Omron CX-Programmer project NewProject (CX-Programmer 9.41)

# PLC NewPLC1: CJ2M CPU12
I/O table (CPU CJ2M-CPU12): rack 0 slot 0 CJ1W-ETN21(ETN21Mode)

## Program NewProgram1 (cyclic task 0)
Local symbols
ETN_CloseRequest 1522.13 BOOL  ; ETN Unit close request dedicated control bit
ETN_DestinationIPAddress2 D30091 UINT  ; ETN Unit destination IP address
ETN_DestinationPortNo D30092 UINT  ; ETN Unit destination port No.
ETN_LocalPortNo D30089 UINT  ; ETN Unit local port No.
ETN_NoOfBytesToSendReceive D30093 INT  ; ETN Unit No. of bytes to send/receive
ETN_OpenRequest 1522.10 BOOL  ; ETN Unit TCP open request (ACTIVE) dedicated control bit
ETN_ReceiveData 1516.13 BOOL  ; ETN Unit receive data presence/absence detection bit
ETN_ReceiveRequest 1522.12 BOOL  ; ETN Unit receive request dedicated control bit
ETN_ResponseCode D30097 UINT  ; ETN Unit response code
ETN_SendReceiveDataAddress1 D30094 UINT  ; ETN Unit send/receive data address
ETN_SendReceiveDataAddress2 D30095 UINT  ; ETN Unit send/receive data address
ETN_SendRequest 1522.11 BOOL  ; ETN Unit send request dedicated control bit
ETN_SocketNo8 D30088 UINT  ; ETN Unit socket option/socket No.8
ETN_TCPConnectionStatus D30016 UINT  ; ETN Unit TCP connection status
ETN_TCPNoOfBytesToReceive D30008 UINT  ; ETN Unit TCP No of bytes to receive
ETN_TimeoutValue D30096 UINT  ; ETN Unit timeout value
Input_CloseMonitoringTime_BCD 5013 UINT_BCD  ; Close monitoring time (BCD)
Input_NoOfBytesToSend D9000 UINT  ; No. of bytes to send
Input_OpenMonitoringTime_BCD 5010 UINT_BCD  ; Open monitoring time (BCD)
Input_ReceiveMonitoringTime_BCD 5012 UINT_BCD  ; Receive monitoring time (BCD)
Input_ReceiveProcessingRequiredNotRequired 5020 UINT  ; Receive processing required/not required setting for send processing
Input_ReceiveWaitingTime_BIN 5014 UINT  ; Receive waiting time (BIN)
Input_SendData D9001 WORD[128]  ; Send data
Input_SendMonitoringTime_BCD 5011 UINT_BCD  ; Send monitoring time (BCD)
Input_Start 5000.00 BOOL  ; Communication processing start switch (turn ON manually)
Local_CloseErrorEnd 5004.02 BOOL  ; Error end->[Communications end]
Local_CloseExecuting 5004.00 BOOL  ; Retain ON status until close processing is completed
Local_CloseMonitoringTimerON T1003 BOOL  ; Close processing monitoring timer
Local_CloseNormalEnd 5004.01 BOOL  ; Normal end->[Communications end]
Local_CloseResponseCodeError 5004.03 BOOL  ; Response code error
Local_CloseStatusError 5004.05 BOOL  ; TCP close status error
Local_CloseTimeout 5004.04 BOOL  ; Timeout
Local_CommunicationsInProgress 5000.01 BOOL  ; Retain ON status until communication processing is completed->[Open processing]
Local_FirstReceiveWord 5111 INT  ; First receive word
Local_FirstReceiveWordDivisionRemainder 5113 INT  ; First receive word division remainder
Local_FirstReceiveWordOffset 5112 INT  ; First receive word offset
Local_FirstSendWord 5031 UINT  ; First send word
Local_InitialSettingCompleted 5000.04 BOOL  ; Initialization setting completion->[Open processing]
Local_OpenErrorEnd 5001.02 BOOL  ; Error end->[Close processing]
Local_OpenExecuting 5001.00 BOOL  ; Retain ON status until open processing is completed
Local_OpenMonitoringTimerON T1000 BOOL  ; Open processing monitoring timer
Local_OpenNormalEnd 5001.01 BOOL  ; Normal end->[Send processing]
Local_OpenResponseCodeError 5001.03 BOOL  ; Response code error
Local_OpenTimeout 5001.04 BOOL  ; Timeout
Local_ReceiveDataAddressType 5110 UINT  ; Receive data address type
Local_ReceiveDataJudgmentArea_UNIT 5114 UINT  ; Area used to convert receive data into UNIT type and to determine the result
Local_ReceiveDestinationDeviceError 5003.05 BOOL  ; Destination device error
Local_ReceiveErrorEnd 5003.02 BOOL  ; Error end->[Close processing]
Local_ReceiveExecuting 5003.00 BOOL  ; Retain ON status until receive processing is completed
Local_ReceiveMonitoringTimerON T1002 BOOL  ; Receive processing monitoring timer
Local_ReceiveNormalEnd 5003.01 BOOL  ; Normal end->[Close processing]
Local_ReceiveProcessingNotRequired 5000.03 BOOL  ; After send processing, skip receive processing and executes close processing
Local_ReceiveProcessingRequired 5000.02 BOOL  ; After send processing, execute receive processing
Local_ReceiveRepeatON 5003.06 BOOL  ; Repeat receive request
Local_ReceiveRequestON 5003.07 BOOL  ; Receive request repeating ON<->OFF bit
Local_ReceiveResponseCodeError 5003.03 BOOL  ; Response code error
Local_ReceiveTimeout 5003.04 BOOL  ; Timeout
Local_SendDataAddressType 5030 UINT  ; Send data address type
Local_SendErrorEnd 5002.02 BOOL  ; Error end->[Close processing]
Local_SendExecuting 5002.00 BOOL  ; Retain ON status until send processing is completed
Local_SendMonitoringTimerON T1001 BOOL  ; Send processing monitoring timer
Local_SendNormalEnd 5002.01 BOOL  ; Normal end->[Receive processing]
Local_SendResponseCodeError 5002.03 BOOL  ; Response code error
Local_SendTimeout 5002.04 BOOL  ; Timeout
Local_TCPConnectionStatus 5005 UINT  ; TCP connection status determination area
Output_CloseErrorCode H404 WORD  ; Close processing response code/timeout code
Output_DestinationDeviceErrorCode H403 WORD  ; Destination device response code/error code
Output_NoOfBytesToReceive D10000 INT  ; No. of bytes to receive storage area
Output_OpenErrorCode H400 WORD  ; Open processing response code/timeout code
Output_ReceiveData D10001 WORD[2000]  ; Receive data storage area
Output_ReceiveErrorCode H402 WORD  ; Receive processing response code/timeout code
Output_SendErrorCode H401 WORD  ; Send processing response code/timeout code
TN_DestinationIPAddress1 D30090 UINT  ; ETN Unit destination IP address

### Section Start_Set

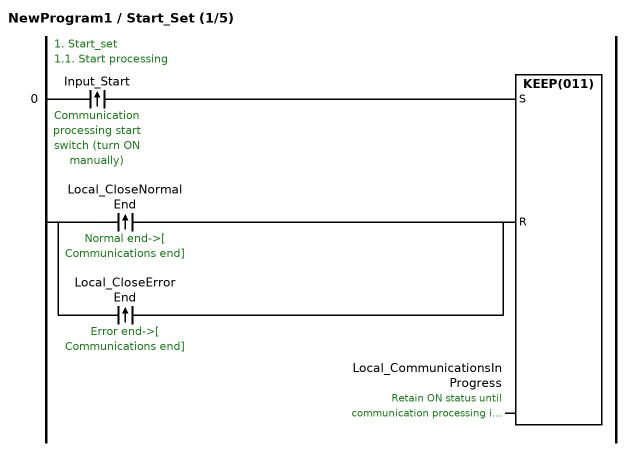
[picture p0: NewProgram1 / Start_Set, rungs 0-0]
; rung 0: 1. Start_set / 1.1. Start processing
@LD Input_Start  ; Communication processing start switch (turn ON manually)
@LD Local_CloseNormalEnd  ; Normal end->[Communications end]
@OR Local_CloseErrorEnd  ; Error end->[Communications end]
KEEP(011) Local_CommunicationsInProgress  ; Retain ON status until communication processing is completed->[Open processing]

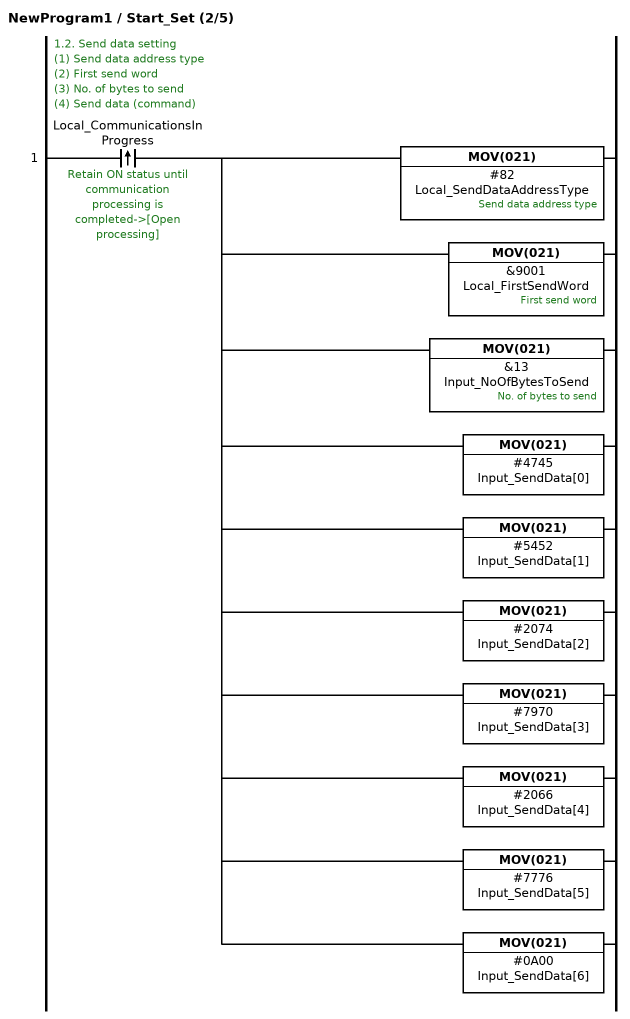
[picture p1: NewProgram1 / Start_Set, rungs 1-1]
; rung 1: 1.2. Send data setting / (1) Send data address type / (2) First send word / (3) No. of bytes to send / (4) Send data (command)
@LD Local_CommunicationsInProgress  ; Retain ON status until communication processing is completed->[Open processing]
MOV(021) #82 Local_SendDataAddressType  ; Send data address type
MOV(021) &9001 Local_FirstSendWord  ; First send word
MOV(021) &13 Input_NoOfBytesToSend  ; No. of bytes to send
MOV(021) #4745 Input_SendData[0]
MOV(021) #5452 Input_SendData[1]
MOV(021) #2074 Input_SendData[2]
MOV(021) #7970 Input_SendData[3]
MOV(021) #2066 Input_SendData[4]
MOV(021) #7776 Input_SendData[5]
MOV(021) #0A00 Input_SendData[6]

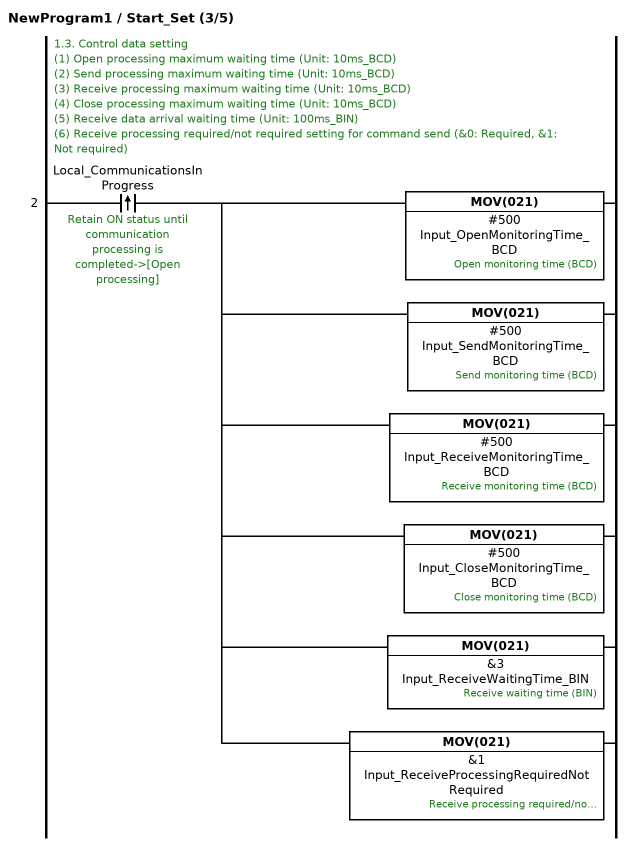
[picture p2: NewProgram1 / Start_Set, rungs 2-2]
; rung 2: 1.3. Control data setting / (1) Open processing maximum waiting time (Unit: 10ms_BCD) / (2) Send processing maximum waiting time (Unit: 10ms_BCD) / (3) Receive processing maximum waiting time (Unit: 10ms_BCD) / (4) Close processing maximum waiting time (Unit: 10ms_BCD) / (5) Receive data arrival waiting time (Unit: 100ms_BIN) / (6) Receive processing required/not required setting for command send (&0: Required, &1: Not required)
@LD Local_CommunicationsInProgress  ; Retain ON status until communication processing is completed->[Open processing]
MOV(021) #500 Input_OpenMonitoringTime_BCD  ; Open monitoring time (BCD)
MOV(021) #500 Input_SendMonitoringTime_BCD  ; Send monitoring time (BCD)
MOV(021) #500 Input_ReceiveMonitoringTime_BCD  ; Receive monitoring time (BCD)
MOV(021) #500 Input_CloseMonitoringTime_BCD  ; Close monitoring time (BCD)
MOV(021) &3 Input_ReceiveWaitingTime_BIN  ; Receive waiting time (BIN)
MOV(021) &1 Input_ReceiveProcessingRequiredNotRequired  ; Receive processing required/not required setting for send processing

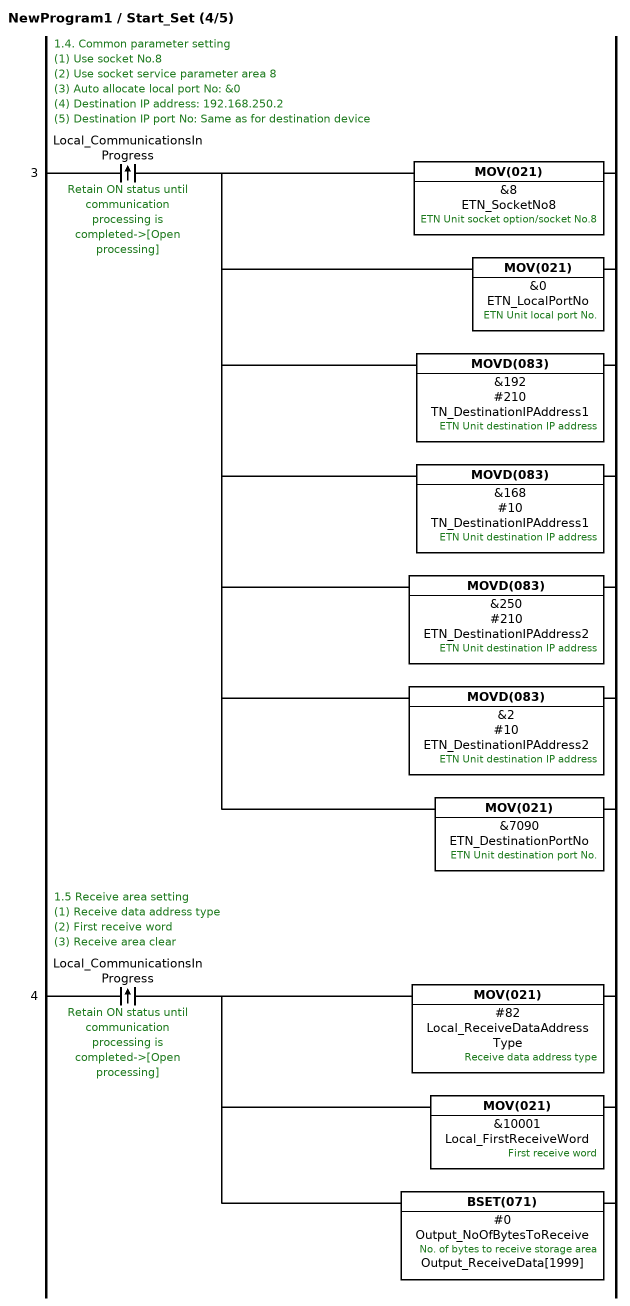
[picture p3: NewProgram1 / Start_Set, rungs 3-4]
; rung 3: 1.4. Common parameter setting / (1) Use socket No.8 / (2) Use socket service parameter area 8 / (3) Auto allocate local port No: &0 / (4) Destination IP address: 192.168.250.2 / (5) Destination IP port No: Same as for destination device
@LD Local_CommunicationsInProgress  ; Retain ON status until communication processing is completed->[Open processing]
MOV(021) &8 ETN_SocketNo8  ; ETN Unit socket option/socket No.8
MOV(021) &0 ETN_LocalPortNo  ; ETN Unit local port No.
MOVD(083) &192 #210 TN_DestinationIPAddress1  ; ETN Unit destination IP address
MOVD(083) &168 #10 TN_DestinationIPAddress1  ; ETN Unit destination IP address
MOVD(083) &250 #210 ETN_DestinationIPAddress2  ; ETN Unit destination IP address
MOVD(083) &2 #10 ETN_DestinationIPAddress2  ; ETN Unit destination IP address
MOV(021) &7090 ETN_DestinationPortNo  ; ETN Unit destination port No.
; rung 4: 1.5 Receive area setting / (1) Receive data address type / (2) First receive word / (3) Receive area clear
@LD Local_CommunicationsInProgress  ; Retain ON status until communication processing is completed->[Open processing]
MOV(021) #82 Local_ReceiveDataAddressType  ; Receive data address type
MOV(021) &10001 Local_FirstReceiveWord  ; First receive word
BSET(071) #0 Output_NoOfBytesToReceive Output_ReceiveData[1999]  ; No. of bytes to receive storage area

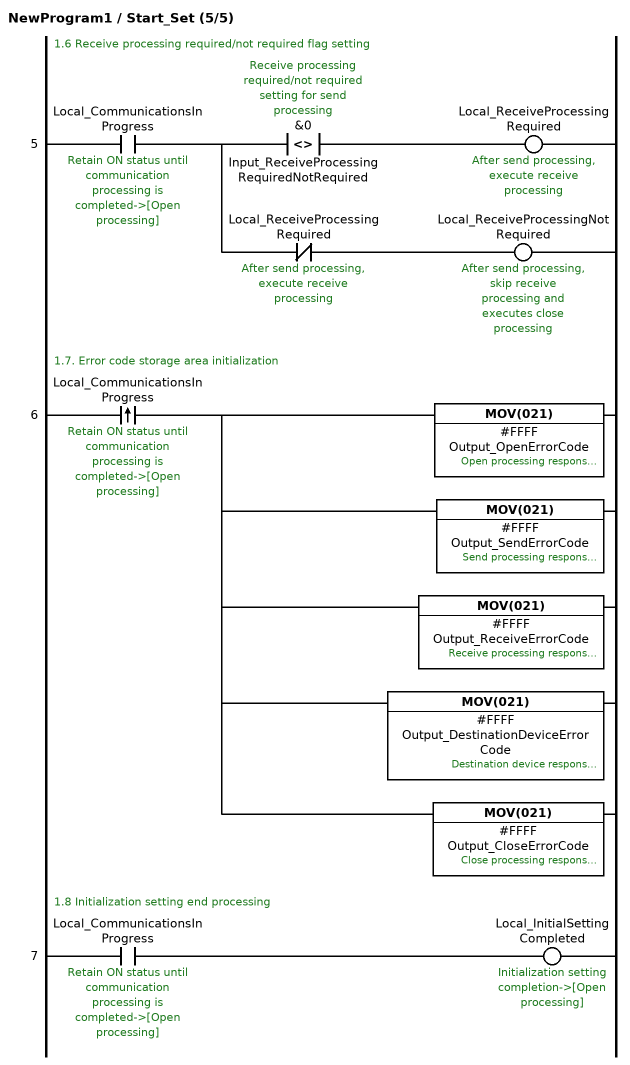
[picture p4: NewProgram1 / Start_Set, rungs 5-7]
; rung 5: 1.6 Receive processing required/not required flag setting
LD Local_CommunicationsInProgress  ; Retain ON status until communication processing is completed->[Open processing]
OUT TR0
AND<>(305) &0 Input_ReceiveProcessingRequiredNotRequired  ; Receive processing required/not required setting for send processing
OUT Local_ReceiveProcessingRequired  ; After send processing, execute receive processing
LD TR0
ANDNOT Local_ReceiveProcessingRequired  ; After send processing, execute receive processing
OUT Local_ReceiveProcessingNotRequired  ; After send processing, skip receive processing and executes close processing
; rung 6: 1.7. Error code storage area initialization
@LD Local_CommunicationsInProgress  ; Retain ON status until communication processing is completed->[Open processing]
MOV(021) #FFFF Output_OpenErrorCode  ; Open processing response code/timeout code
MOV(021) #FFFF Output_SendErrorCode  ; Send processing response code/timeout code
MOV(021) #FFFF Output_ReceiveErrorCode  ; Receive processing response code/timeout code
MOV(021) #FFFF Output_DestinationDeviceErrorCode  ; Destination device response code/error code
MOV(021) #FFFF Output_CloseErrorCode  ; Close processing response code/timeout code
; rung 7: 1.8 Initialization setting end processing
LD Local_CommunicationsInProgress  ; Retain ON status until communication processing is completed->[Open processing]
OUT Local_InitialSettingCompleted  ; Initialization setting completion->[Open processing]

### Section Open_Processing

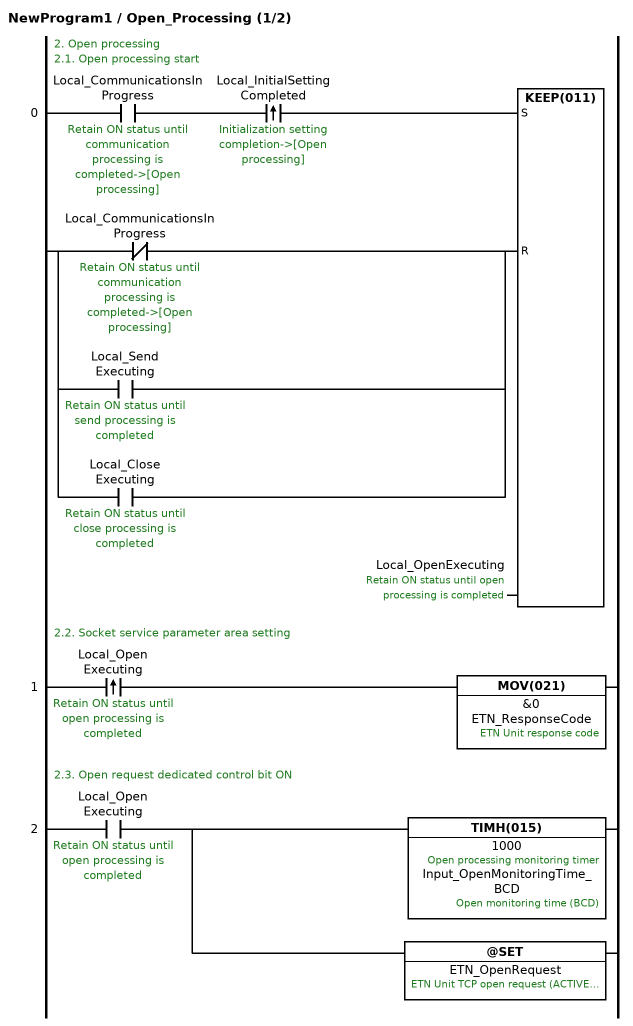
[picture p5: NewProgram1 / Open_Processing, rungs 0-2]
; rung 0: 2. Open processing / 2.1. Open processing start
LD Local_CommunicationsInProgress  ; Retain ON status until communication processing is completed->[Open processing]
@AND Local_InitialSettingCompleted  ; Initialization setting completion->[Open processing]
LDNOT Local_CommunicationsInProgress  ; Retain ON status until communication processing is completed->[Open processing]
OR Local_SendExecuting  ; Retain ON status until send processing is completed
OR Local_CloseExecuting  ; Retain ON status until close processing is completed
KEEP(011) Local_OpenExecuting  ; Retain ON status until open processing is completed
; rung 1: 2.2. Socket service parameter area setting
@LD Local_OpenExecuting  ; Retain ON status until open processing is completed
MOV(021) &0 ETN_ResponseCode  ; ETN Unit response code
; rung 2: 2.3. Open request dedicated control bit ON
LD Local_OpenExecuting  ; Retain ON status until open processing is completed
TIMH(015) 1000 Input_OpenMonitoringTime_BCD  ; Open monitoring time (BCD), Open processing monitoring timer
@SET ETN_OpenRequest  ; ETN Unit TCP open request (ACTIVE) dedicated control bit

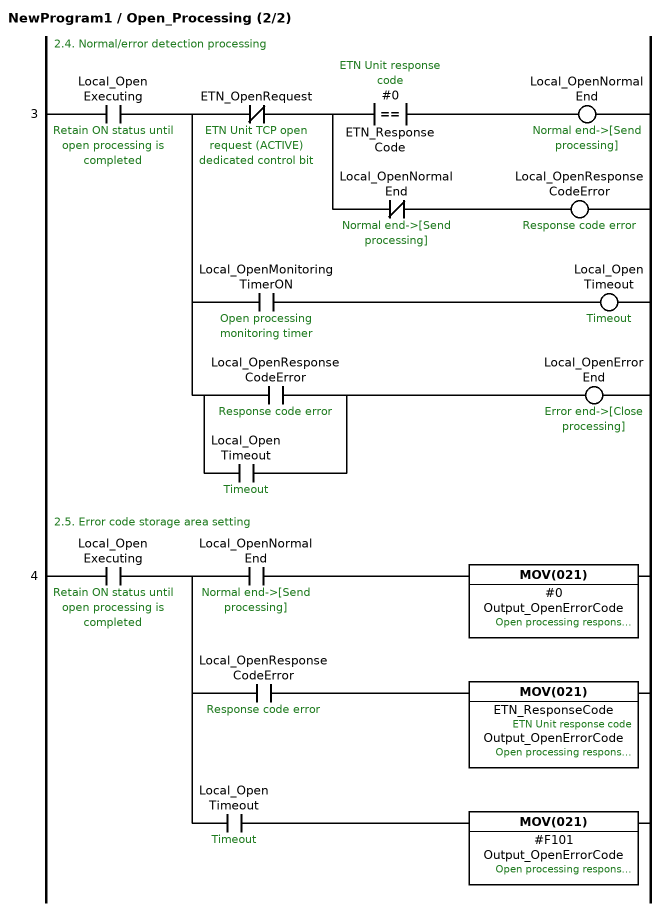
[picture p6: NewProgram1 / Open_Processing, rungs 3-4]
; rung 3: 2.4. Normal/error detection processing
LD Local_OpenExecuting  ; Retain ON status until open processing is completed
OUT TR0
ANDNOT ETN_OpenRequest  ; ETN Unit TCP open request (ACTIVE) dedicated control bit
OUT TR1
AND=(300) #0 ETN_ResponseCode  ; ETN Unit response code
OUT Local_OpenNormalEnd  ; Normal end->[Send processing]
LD TR1
ANDNOT Local_OpenNormalEnd  ; Normal end->[Send processing]
OUT Local_OpenResponseCodeError  ; Response code error
LD TR0
AND Local_OpenMonitoringTimerON  ; Open processing monitoring timer
OUT Local_OpenTimeout  ; Timeout
LD TR0
LD Local_OpenResponseCodeError  ; Response code error
OR Local_OpenTimeout  ; Timeout
ANDLD
OUT Local_OpenErrorEnd  ; Error end->[Close processing]
; rung 4: 2.5. Error code storage area setting
LD Local_OpenExecuting  ; Retain ON status until open processing is completed
OUT TR0
AND Local_OpenNormalEnd  ; Normal end->[Send processing]
MOV(021) #0 Output_OpenErrorCode  ; Open processing response code/timeout code
LD TR0
AND Local_OpenResponseCodeError  ; Response code error
MOV(021) ETN_ResponseCode Output_OpenErrorCode  ; ETN Unit response code, Open processing response code/timeout code
LD TR0
AND Local_OpenTimeout  ; Timeout
MOV(021) #F101 Output_OpenErrorCode  ; Open processing response code/timeout code

### Section Send_Processing

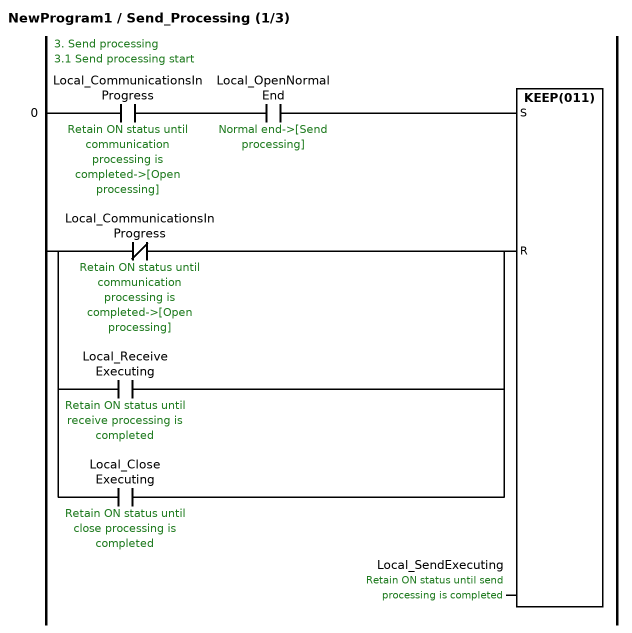
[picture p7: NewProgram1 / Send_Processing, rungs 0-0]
; rung 0: 3. Send processing / 3.1 Send processing start
LD Local_CommunicationsInProgress  ; Retain ON status until communication processing is completed->[Open processing]
AND Local_OpenNormalEnd  ; Normal end->[Send processing]
LDNOT Local_CommunicationsInProgress  ; Retain ON status until communication processing is completed->[Open processing]
OR Local_ReceiveExecuting  ; Retain ON status until receive processing is completed
OR Local_CloseExecuting  ; Retain ON status until close processing is completed
KEEP(011) Local_SendExecuting  ; Retain ON status until send processing is completed

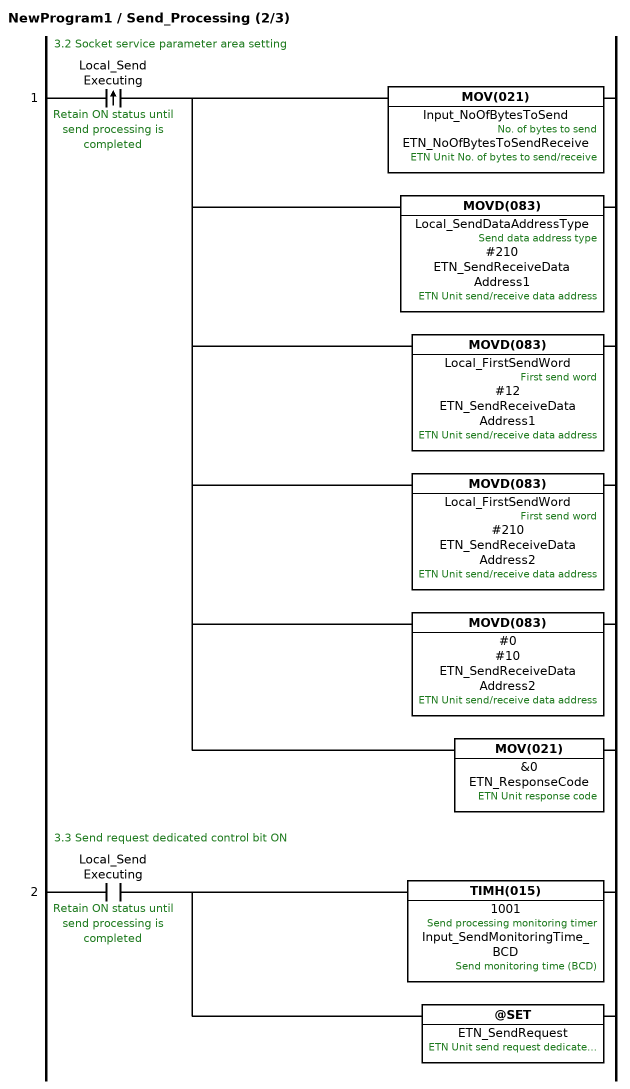
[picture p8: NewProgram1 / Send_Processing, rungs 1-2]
; rung 1: 3.2 Socket service parameter area setting
@LD Local_SendExecuting  ; Retain ON status until send processing is completed
MOV(021) Input_NoOfBytesToSend ETN_NoOfBytesToSendReceive  ; No. of bytes to send, ETN Unit No. of bytes to send/receive
MOVD(083) Local_SendDataAddressType #210 ETN_SendReceiveDataAddress1  ; Send data address type, ETN Unit send/receive data address
MOVD(083) Local_FirstSendWord #12 ETN_SendReceiveDataAddress1  ; First send word, ETN Unit send/receive data address
MOVD(083) Local_FirstSendWord #210 ETN_SendReceiveDataAddress2  ; First send word, ETN Unit send/receive data address
MOVD(083) #0 #10 ETN_SendReceiveDataAddress2  ; ETN Unit send/receive data address
MOV(021) &0 ETN_ResponseCode  ; ETN Unit response code
; rung 2: 3.3 Send request dedicated control bit ON
LD Local_SendExecuting  ; Retain ON status until send processing is completed
TIMH(015) 1001 Input_SendMonitoringTime_BCD  ; Send monitoring time (BCD), Send processing monitoring timer
@SET ETN_SendRequest  ; ETN Unit send request dedicated control bit

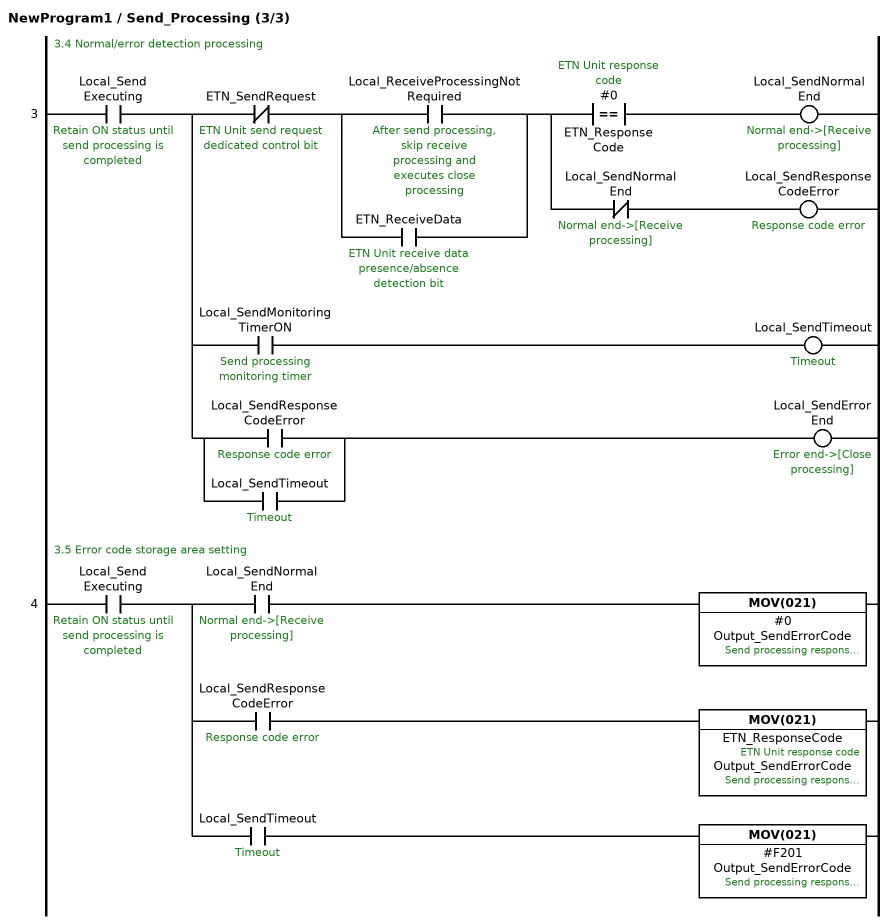
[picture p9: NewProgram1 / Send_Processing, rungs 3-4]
; rung 3: 3.4 Normal/error detection processing
LD Local_SendExecuting  ; Retain ON status until send processing is completed
OUT TR0
ANDNOT ETN_SendRequest  ; ETN Unit send request dedicated control bit
LD Local_ReceiveProcessingNotRequired  ; After send processing, skip receive processing and executes close processing
OR ETN_ReceiveData  ; ETN Unit receive data presence/absence detection bit
ANDLD
OUT TR1
AND=(300) #0 ETN_ResponseCode  ; ETN Unit response code
OUT Local_SendNormalEnd  ; Normal end->[Receive processing]
LD TR1
ANDNOT Local_SendNormalEnd  ; Normal end->[Receive processing]
OUT Local_SendResponseCodeError  ; Response code error
LD TR0
AND Local_SendMonitoringTimerON  ; Send processing monitoring timer
OUT Local_SendTimeout  ; Timeout
LD TR0
LD Local_SendResponseCodeError  ; Response code error
OR Local_SendTimeout  ; Timeout
ANDLD
OUT Local_SendErrorEnd  ; Error end->[Close processing]
; rung 4: 3.5 Error code storage area setting
LD Local_SendExecuting  ; Retain ON status until send processing is completed
OUT TR0
AND Local_SendNormalEnd  ; Normal end->[Receive processing]
MOV(021) #0 Output_SendErrorCode  ; Send processing response code/timeout code
LD TR0
AND Local_SendResponseCodeError  ; Response code error
MOV(021) ETN_ResponseCode Output_SendErrorCode  ; ETN Unit response code, Send processing response code/timeout code
LD TR0
AND Local_SendTimeout  ; Timeout
MOV(021) #F201 Output_SendErrorCode  ; Send processing response code/timeout code

### Section Receive_Processing

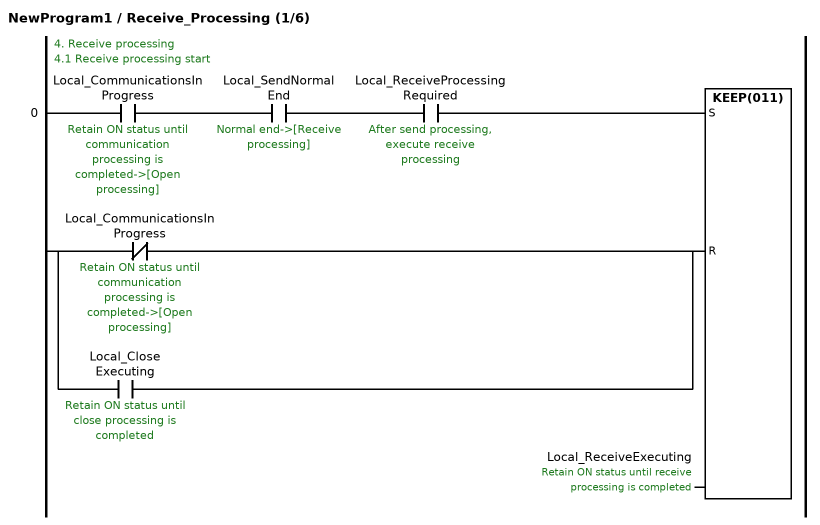
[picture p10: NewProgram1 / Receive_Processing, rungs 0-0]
; rung 0: 4. Receive processing / 4.1 Receive processing start
LD Local_CommunicationsInProgress  ; Retain ON status until communication processing is completed->[Open processing]
AND Local_SendNormalEnd  ; Normal end->[Receive processing]
AND Local_ReceiveProcessingRequired  ; After send processing, execute receive processing
LDNOT Local_CommunicationsInProgress  ; Retain ON status until communication processing is completed->[Open processing]
OR Local_CloseExecuting  ; Retain ON status until close processing is completed
KEEP(011) Local_ReceiveExecuting  ; Retain ON status until receive processing is completed

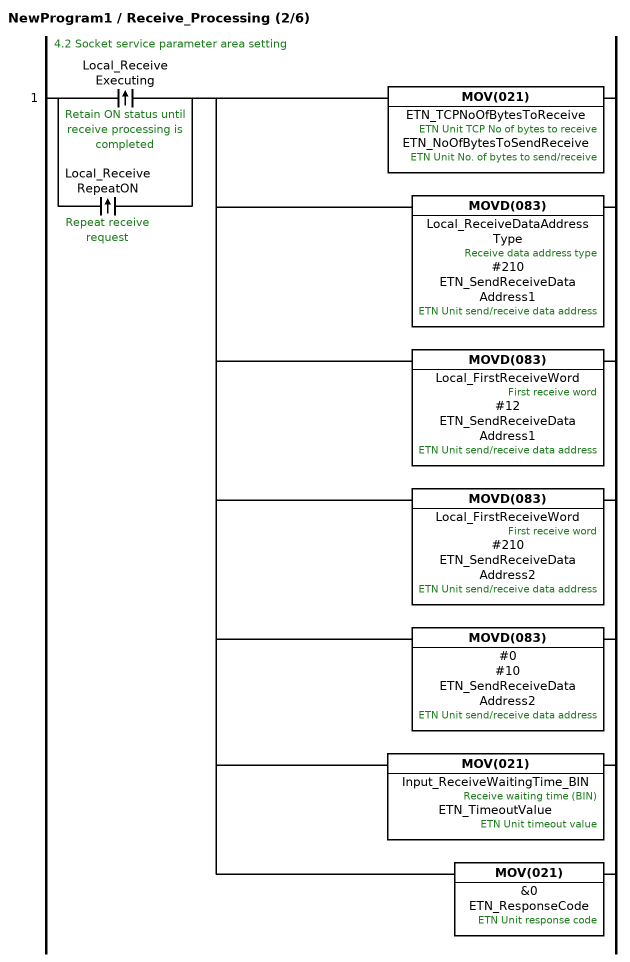
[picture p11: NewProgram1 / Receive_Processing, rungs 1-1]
; rung 1: 4.2 Socket service parameter area setting
@LD Local_ReceiveExecuting  ; Retain ON status until receive processing is completed
@OR Local_ReceiveRepeatON  ; Repeat receive request
MOV(021) ETN_TCPNoOfBytesToReceive ETN_NoOfBytesToSendReceive  ; ETN Unit TCP No of bytes to receive, ETN Unit No. of bytes to send/receive
MOVD(083) Local_ReceiveDataAddressType #210 ETN_SendReceiveDataAddress1  ; Receive data address type, ETN Unit send/receive data address
MOVD(083) Local_FirstReceiveWord #12 ETN_SendReceiveDataAddress1  ; First receive word, ETN Unit send/receive data address
MOVD(083) Local_FirstReceiveWord #210 ETN_SendReceiveDataAddress2  ; First receive word, ETN Unit send/receive data address
MOVD(083) #0 #10 ETN_SendReceiveDataAddress2  ; ETN Unit send/receive data address
MOV(021) Input_ReceiveWaitingTime_BIN ETN_TimeoutValue  ; Receive waiting time (BIN), ETN Unit timeout value
MOV(021) &0 ETN_ResponseCode  ; ETN Unit response code

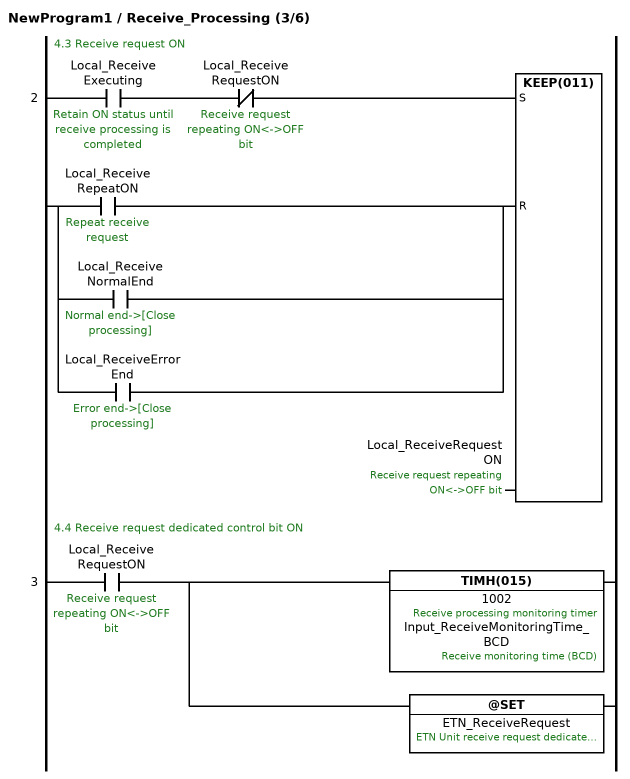
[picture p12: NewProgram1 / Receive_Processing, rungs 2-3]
; rung 2: 4.3 Receive request ON
LD Local_ReceiveExecuting  ; Retain ON status until receive processing is completed
ANDNOT Local_ReceiveRequestON  ; Receive request repeating ON<->OFF bit
LD Local_ReceiveRepeatON  ; Repeat receive request
OR Local_ReceiveNormalEnd  ; Normal end->[Close processing]
OR Local_ReceiveErrorEnd  ; Error end->[Close processing]
KEEP(011) Local_ReceiveRequestON  ; Receive request repeating ON<->OFF bit
; rung 3: 4.4 Receive request dedicated control bit ON
LD Local_ReceiveRequestON  ; Receive request repeating ON<->OFF bit
TIMH(015) 1002 Input_ReceiveMonitoringTime_BCD  ; Receive monitoring time (BCD), Receive processing monitoring timer
@SET ETN_ReceiveRequest  ; ETN Unit receive request dedicated control bit

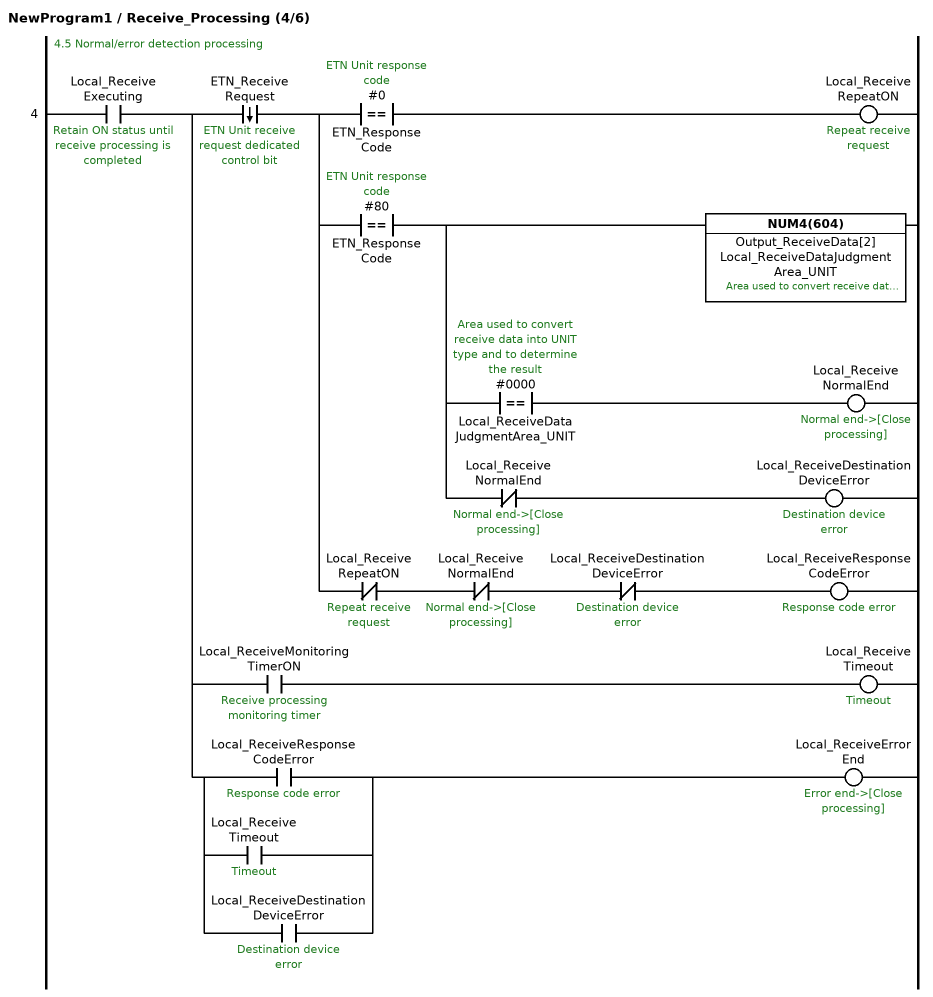
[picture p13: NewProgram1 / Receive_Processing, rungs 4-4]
; rung 4: 4.5 Normal/error detection processing
LD Local_ReceiveExecuting  ; Retain ON status until receive processing is completed
OUT TR0
%AND ETN_ReceiveRequest  ; ETN Unit receive request dedicated control bit
OUT TR1
AND=(300) #0 ETN_ResponseCode  ; ETN Unit response code
OUT Local_ReceiveRepeatON  ; Repeat receive request
LD TR1
AND=(300) #80 ETN_ResponseCode  ; ETN Unit response code
OUT TR2
NUM4(604) Output_ReceiveData[2] Local_ReceiveDataJudgmentArea_UNIT  ; Area used to convert receive data into UNIT type and to determine the result
AND=(300) #0000 Local_ReceiveDataJudgmentArea_UNIT  ; Area used to convert receive data into UNIT type and to determine the result
OUT Local_ReceiveNormalEnd  ; Normal end->[Close processing]
LD TR2
ANDNOT Local_ReceiveNormalEnd  ; Normal end->[Close processing]
OUT Local_ReceiveDestinationDeviceError  ; Destination device error
LD TR1
ANDNOT Local_ReceiveRepeatON  ; Repeat receive request
ANDNOT Local_ReceiveNormalEnd  ; Normal end->[Close processing]
ANDNOT Local_ReceiveDestinationDeviceError  ; Destination device error
OUT Local_ReceiveResponseCodeError  ; Response code error
LD TR0
AND Local_ReceiveMonitoringTimerON  ; Receive processing monitoring timer
OUT Local_ReceiveTimeout  ; Timeout
LD TR0
LD Local_ReceiveResponseCodeError  ; Response code error
OR Local_ReceiveTimeout  ; Timeout
OR Local_ReceiveDestinationDeviceError  ; Destination device error
ANDLD
OUT Local_ReceiveErrorEnd  ; Error end->[Close processing]

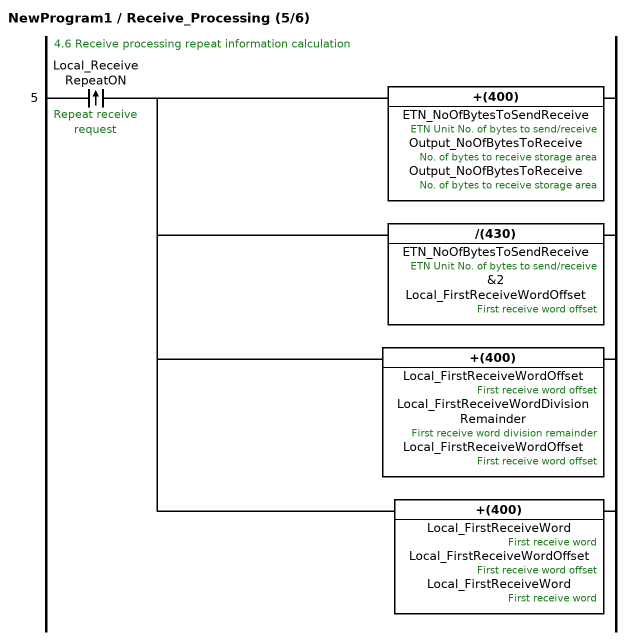
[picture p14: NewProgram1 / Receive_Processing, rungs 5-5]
; rung 5: 4.6 Receive processing repeat information calculation
@LD Local_ReceiveRepeatON  ; Repeat receive request
+(400) ETN_NoOfBytesToSendReceive Output_NoOfBytesToReceive Output_NoOfBytesToReceive  ; ETN Unit No. of bytes to send/receive, No. of bytes to receive storage area
/(430) ETN_NoOfBytesToSendReceive &2 Local_FirstReceiveWordOffset  ; ETN Unit No. of bytes to send/receive, First receive word offset
+(400) Local_FirstReceiveWordOffset Local_FirstReceiveWordDivisionRemainder Local_FirstReceiveWordOffset  ; First receive word offset, First receive word division remainder
+(400) Local_FirstReceiveWord Local_FirstReceiveWordOffset Local_FirstReceiveWord  ; First receive word, First receive word offset

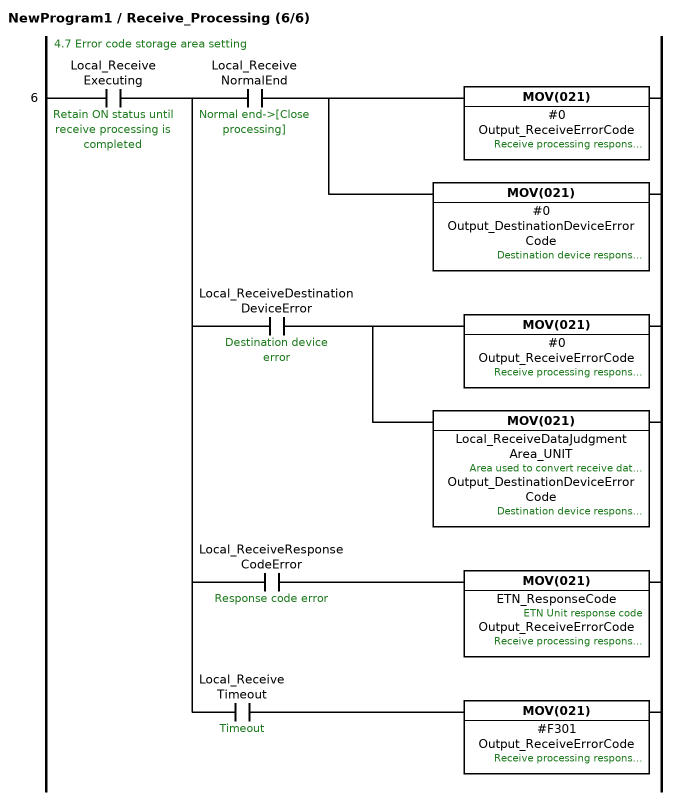
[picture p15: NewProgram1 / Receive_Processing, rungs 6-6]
; rung 6: 4.7 Error code storage area setting
LD Local_ReceiveExecuting  ; Retain ON status until receive processing is completed
OUT TR0
AND Local_ReceiveNormalEnd  ; Normal end->[Close processing]
MOV(021) #0 Output_ReceiveErrorCode  ; Receive processing response code/timeout code
MOV(021) #0 Output_DestinationDeviceErrorCode  ; Destination device response code/error code
LD TR0
AND Local_ReceiveDestinationDeviceError  ; Destination device error
MOV(021) #0 Output_ReceiveErrorCode  ; Receive processing response code/timeout code
MOV(021) Local_ReceiveDataJudgmentArea_UNIT Output_DestinationDeviceErrorCode  ; Area used to convert receive data into UNIT type and to determine the result, Destination device response code/error code
LD TR0
AND Local_ReceiveResponseCodeError  ; Response code error
MOV(021) ETN_ResponseCode Output_ReceiveErrorCode  ; ETN Unit response code, Receive processing response code/timeout code
LD TR0
AND Local_ReceiveTimeout  ; Timeout
MOV(021) #F301 Output_ReceiveErrorCode  ; Receive processing response code/timeout code

### Section Close_Processing

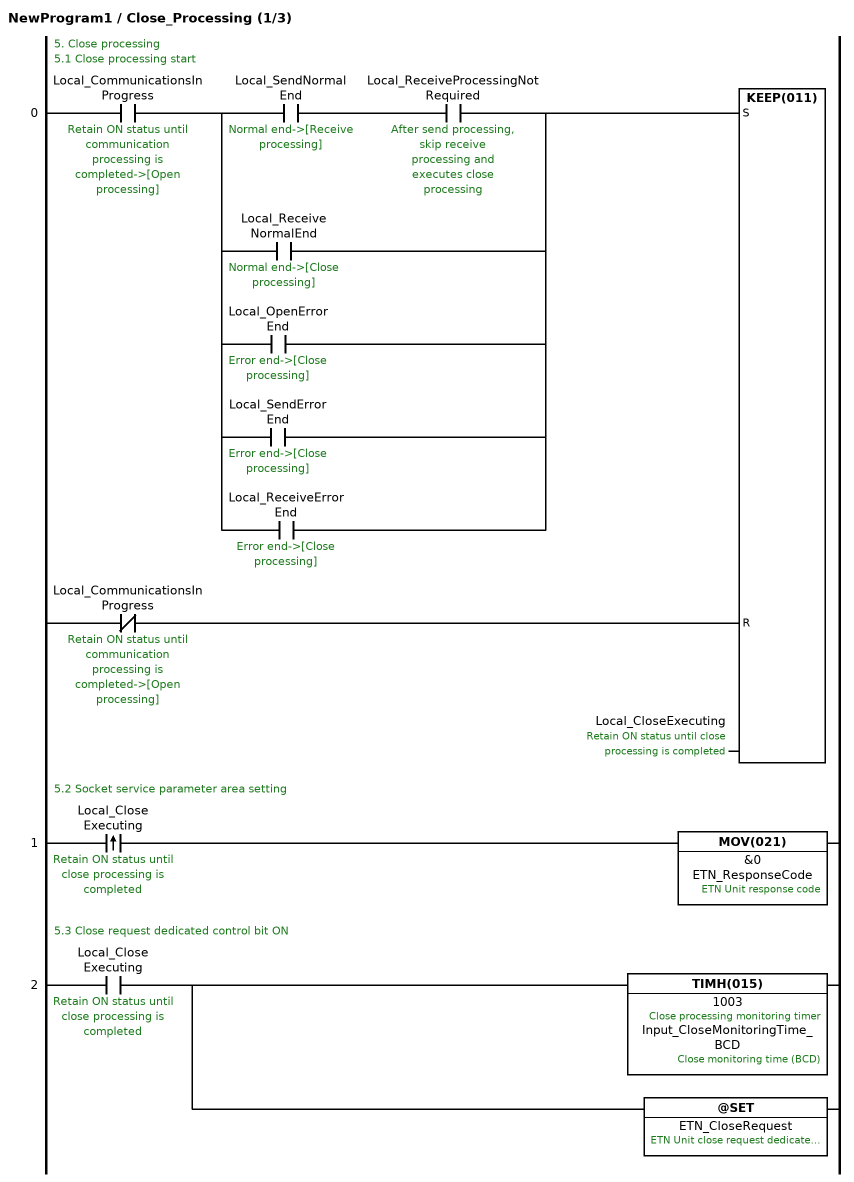
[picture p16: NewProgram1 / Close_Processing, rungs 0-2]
; rung 0: 5. Close processing / 5.1 Close processing start
LD Local_CommunicationsInProgress  ; Retain ON status until communication processing is completed->[Open processing]
LD Local_SendNormalEnd  ; Normal end->[Receive processing]
AND Local_ReceiveProcessingNotRequired  ; After send processing, skip receive processing and executes close processing
OR Local_ReceiveNormalEnd  ; Normal end->[Close processing]
OR Local_OpenErrorEnd  ; Error end->[Close processing]
OR Local_SendErrorEnd  ; Error end->[Close processing]
OR Local_ReceiveErrorEnd  ; Error end->[Close processing]
ANDLD
LDNOT Local_CommunicationsInProgress  ; Retain ON status until communication processing is completed->[Open processing]
KEEP(011) Local_CloseExecuting  ; Retain ON status until close processing is completed
; rung 1: 5.2 Socket service parameter area setting
@LD Local_CloseExecuting  ; Retain ON status until close processing is completed
MOV(021) &0 ETN_ResponseCode  ; ETN Unit response code
; rung 2: 5.3 Close request dedicated control bit ON
LD Local_CloseExecuting  ; Retain ON status until close processing is completed
TIMH(015) 1003 Input_CloseMonitoringTime_BCD  ; Close monitoring time (BCD), Close processing monitoring timer
@SET ETN_CloseRequest  ; ETN Unit close request dedicated control bit

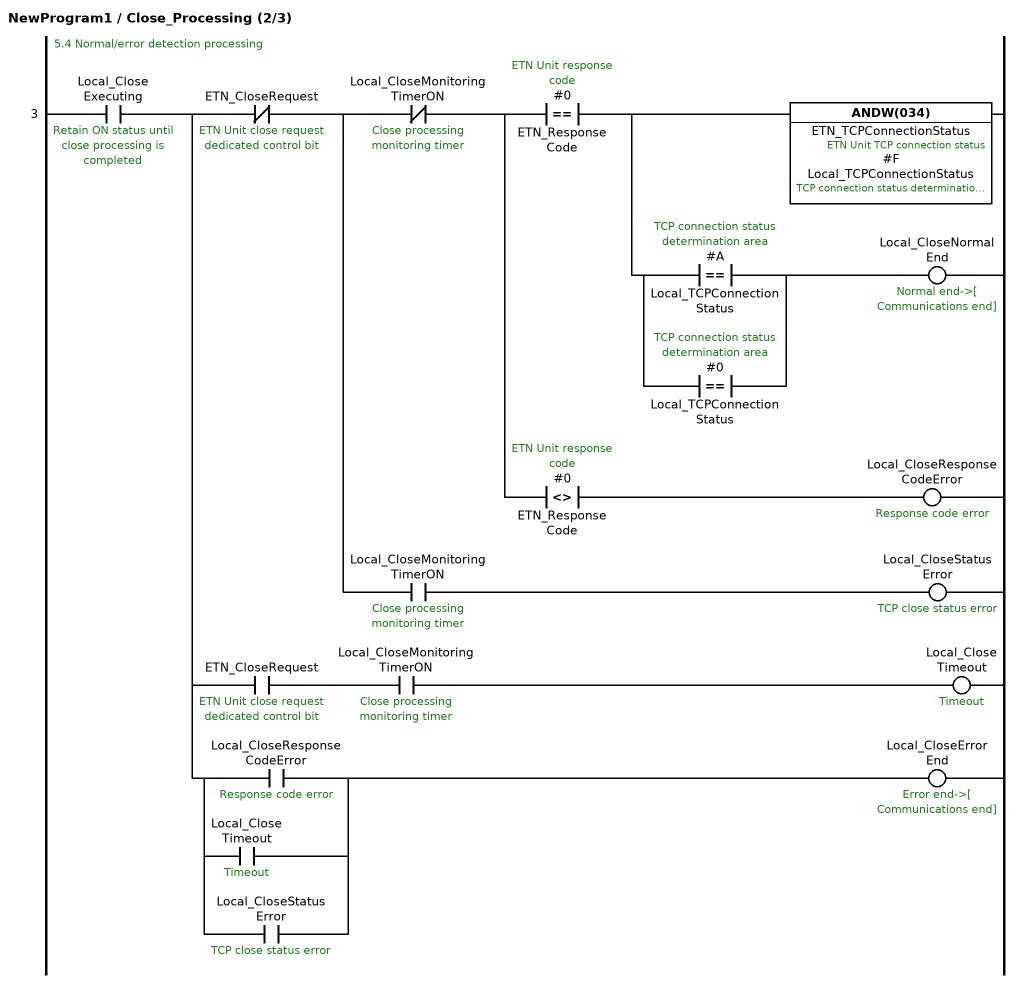
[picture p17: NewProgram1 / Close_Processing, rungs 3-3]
; rung 3: 5.4 Normal/error detection processing
LD Local_CloseExecuting  ; Retain ON status until close processing is completed
OUT TR0
ANDNOT ETN_CloseRequest  ; ETN Unit close request dedicated control bit
OUT TR1
ANDNOT Local_CloseMonitoringTimerON  ; Close processing monitoring timer
OUT TR2
AND=(300) #0 ETN_ResponseCode  ; ETN Unit response code
ANDW(034) ETN_TCPConnectionStatus #F Local_TCPConnectionStatus  ; ETN Unit TCP connection status, TCP connection status determination area
LD=(300) #A Local_TCPConnectionStatus  ; TCP connection status determination area
OR=(300) #0 Local_TCPConnectionStatus  ; TCP connection status determination area
ANDLD
OUT Local_CloseNormalEnd  ; Normal end->[Communications end]
LD TR2
AND<>(305) #0 ETN_ResponseCode  ; ETN Unit response code
OUT Local_CloseResponseCodeError  ; Response code error
LD TR1
AND Local_CloseMonitoringTimerON  ; Close processing monitoring timer
OUT Local_CloseStatusError  ; TCP close status error
LD TR0
AND ETN_CloseRequest  ; ETN Unit close request dedicated control bit
AND Local_CloseMonitoringTimerON  ; Close processing monitoring timer
OUT Local_CloseTimeout  ; Timeout
LD TR0
LD Local_CloseResponseCodeError  ; Response code error
OR Local_CloseTimeout  ; Timeout
OR Local_CloseStatusError  ; TCP close status error
ANDLD
OUT Local_CloseErrorEnd  ; Error end->[Communications end]

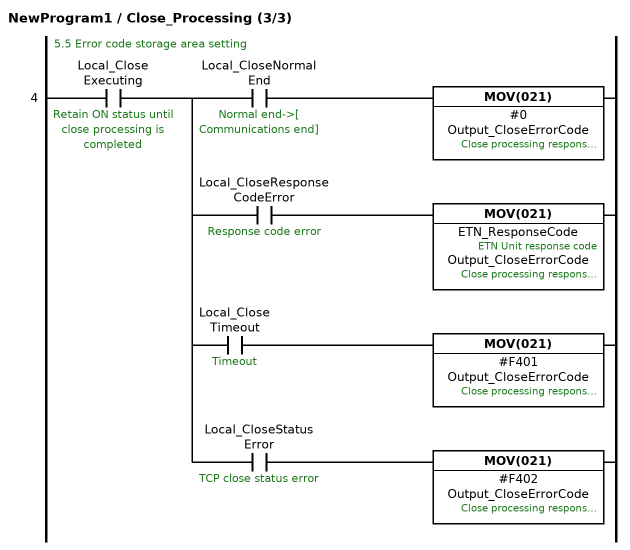
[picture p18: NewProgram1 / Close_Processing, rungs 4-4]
; rung 4: 5.5 Error code storage area setting
LD Local_CloseExecuting  ; Retain ON status until close processing is completed
OUT TR0
AND Local_CloseNormalEnd  ; Normal end->[Communications end]
MOV(021) #0 Output_CloseErrorCode  ; Close processing response code/timeout code
LD TR0
AND Local_CloseResponseCodeError  ; Response code error
MOV(021) ETN_ResponseCode Output_CloseErrorCode  ; ETN Unit response code, Close processing response code/timeout code
LD TR0
AND Local_CloseTimeout  ; Timeout
MOV(021) #F401 Output_CloseErrorCode  ; Close processing response code/timeout code
LD TR0
AND Local_CloseStatusError  ; TCP close status error
MOV(021) #F402 Output_CloseErrorCode  ; Close processing response code/timeout code

### Section END
; rung 0
END(001)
